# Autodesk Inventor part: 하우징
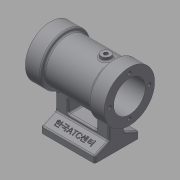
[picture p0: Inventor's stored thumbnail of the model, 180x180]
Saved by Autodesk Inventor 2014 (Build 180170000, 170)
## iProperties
Created: 2018-01
Part Number: 하우징
Material: 알루미늄 6061
Document SubType Name: Modeling
Designer: mduedu
Density: 2.71 g/cm^3
Appearance: 기본값
Mass: 74.6911 g
Surface Area: 127.588 cm^2
Volume: 27.5613 cm^3
Author: mduedu
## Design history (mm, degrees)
sketch "스케치1"
  geometry: L1 (-25, 0)-(25, 0); L2 (-25, 0)-(-25, 16); L3 (-25, 16)-(-15, 16); L4 (-15, 16)-(-15, 14); L5 (-15, 14)-(15, 14); L6 (15, 14)-(15, 16); L7 (15, 16)-(25, 16); L8 (25, 16)-(25, 0); 2 further points
  constraints: 16 end point, 3 parallel, 2 collinear, 2 perpendicular, 1 coincident, 1 horizontal, 1 midpoint, 1 vertical
  dimensions: "d0" = 50 distance of L1.start L1.end; "d2" = 10 distance of L2.end L3.end; "d3" = 10 distance of L6.end L7.end (= d2); "d4" = 32 diameter of L3 L1; "d5" = 28 diameter of L5 L1
revolve "회전1" sketch "스케치1" stored, may be unused: angle "d6" = 90 deg
hole "구멍1" diameter "d9" = 20; stored, may be unused: countersink angle "d13" = 90 deg, drill point angle "d15" = 118 deg; dims "d7" = 10, "d8" = 10, "d10" = 6, "d11" = 4, "d12" = 2, "d14" = 8
fillet "모깎기1" dims "d16" = 1
sketch "스케치2"
  geometry: L1 (0, 0)-(-34, 0); L2 (-34, 14)-(-34, -14); L3 (-34, 14)-(-30, 14); L4 (-30, 14)-(-26, 5); L5 (-26, 5)-(-13.077, 5); L6 (-26, -5)-(-13.077, -5); L7 (-30, -14)-(-26, -5); L8 (-34, -14)-(-30, -14); C1 r 10 at (0, 0) reference; A1 r 14 centre (0, 0) between (-13.077, 5) and (-13.077, -5); 2 further points
  constraints: 16 end point, 3 symmetric about line, 2 perpendicular, 2 point on circle, 1 centre point, 1 coincident, 1 horizontal, 1 midpoint, 1 parallel, 2 other
  dimensions: "d17" = 34 distance of L1.end L1.start; "d18" = 28 distance between parallel lines of L8 L3; "d19" = 10 distance between parallel lines of L6 L5; "d20" = 4 distance of L2.end L7.start; "d21" = 8 distance from line of L6.start L2
extrude "돌출1" join sketch "스케치2" stored distance "d22" = 34; taper "d23" = 0 deg
sketch "스케치3"
  geometry: L1 (-9, -16)-(9, -16); L2 (9, -16)-(9, -24); L3 (9, -24)-(-9, -24); L4 (-9, -24)-(-9, -16); L5 (-17, -15.199)-(-17, -26) reference; L6 (17, -26)-(17, -15.199) reference; L7 (-17, -34)-(17, -34) reference; 1 further point
  constraints: 8 end point, 2 parallel, 1 horizontal, 1 perpendicular
  dimensions: "d24" = 8 distance between parallel lines of L4 L5; "d25" = 8 distance between parallel lines of L2 L6; "d26" = 10 distance between parallel lines of L3 L7; "d27" = 8 distance of L1.end L2.end
extrude "돌출2" cut sketch "스케치3" stored distance "d28" = 34; taper "d29" = 0 deg
fillet "모깎기2" dims "d30" = 1
fillet "모깎기3" dims "d31" = 1
fillet "모깎기4" dims "d32" = 1
fillet "모깎기5" dims "d33" = 1
fillet "모깎기6" dims "d34" = 1
sketch "스케치4"
  geometry: 4 further points
  constraints: 4 other
hole "구멍2" sketch "스케치4" at (-12.5, 0), (0, -12.5), (12.5, 0), (0, 12.5) diameter "d35" = 2.459; stored, may be unused: countersink angle "d39" = 90 deg, drill point angle "d41" = 120 deg; dims "d36" = 5.5, "d37" = 4, "d38" = 2, "d40" = 7
sketch "스케치5"
  geometry: 4 further points
  constraints: 4 other
hole "구멍4" sketch "스케치5" at (-12.5, 0), (0, -12.5), (12.5, 0), (0, 12.5) diameter "d42" = 2.459; stored, may be unused: countersink angle "d46" = 90 deg, drill point angle "d48" = 120 deg; dims "d43" = 5.5, "d44" = 4, "d45" = 2, "d47" = 7
sketch "스케치6"
  geometry: 2 further points
  constraints: 2 other
hole "구멍5" sketch "스케치6" at (7, 14), (25, 14) diameter "d49" = 2.459; stored, may be unused: countersink angle "d53" = 90 deg, drill point angle "d55" = 120 deg; dims "d50" = 6.9, "d51" = 4, "d52" = 2, "d54" = 8.4
node "작업 평면1"
sketch "스케치7"
  geometry: L1 (-25, 16)-(-25, -16) reference; C1 r 3 at (-10, 0); 1 further point
  constraints: 1 centre point, 1 horizontal alignment
  dimensions: "d57" = 6 diameter of C1; "d60" = 15 distance from line of C1.centre L1
extrude "돌출3" join sketch "스케치7" stored distance "d61" = 10; taper "d62" = 0 deg
fillet "모깎기7" dims "d63" = 1
hole "구멍6" diameter "d66" = 2.459; stored, may be unused: countersink angle "d70" = 90 deg, drill point angle "d72" = 118 deg; dims "d64" = 10, "d65" = 10, "d67" = 6, "d68" = 4, "d69" = 2, "d71" = 8
sketch "스케치8"
  geometry: L1 (-1, 0)-(0, 0) reference; L2 (0, 0)-(0, 8.549) reference; L3 (0, 8.549)-(-1, 8.549) reference; L4 (-1, 8.549)-(-1, 0) reference; L5 (32, 0)-(33, 0) reference; L6 (33, 0)-(33, 8.549) reference; L7 (32, 8.549)-(33, 8.549) reference; L8 (32, 8.549)-(32, 0) reference; 3 further points
  constraints: 1 horizontal alignment, 1 midpoint, 1 vertical alignment, 1 other
feature "엠보싱1" sketch "스케치8" dims "d73" = 0.5, "d74" = 0
node "솔리드1"
node "투영된 루프1"
node "투영된 루프2"
node "절단 모서리 투영1"
other parameters: "d56" = 16
